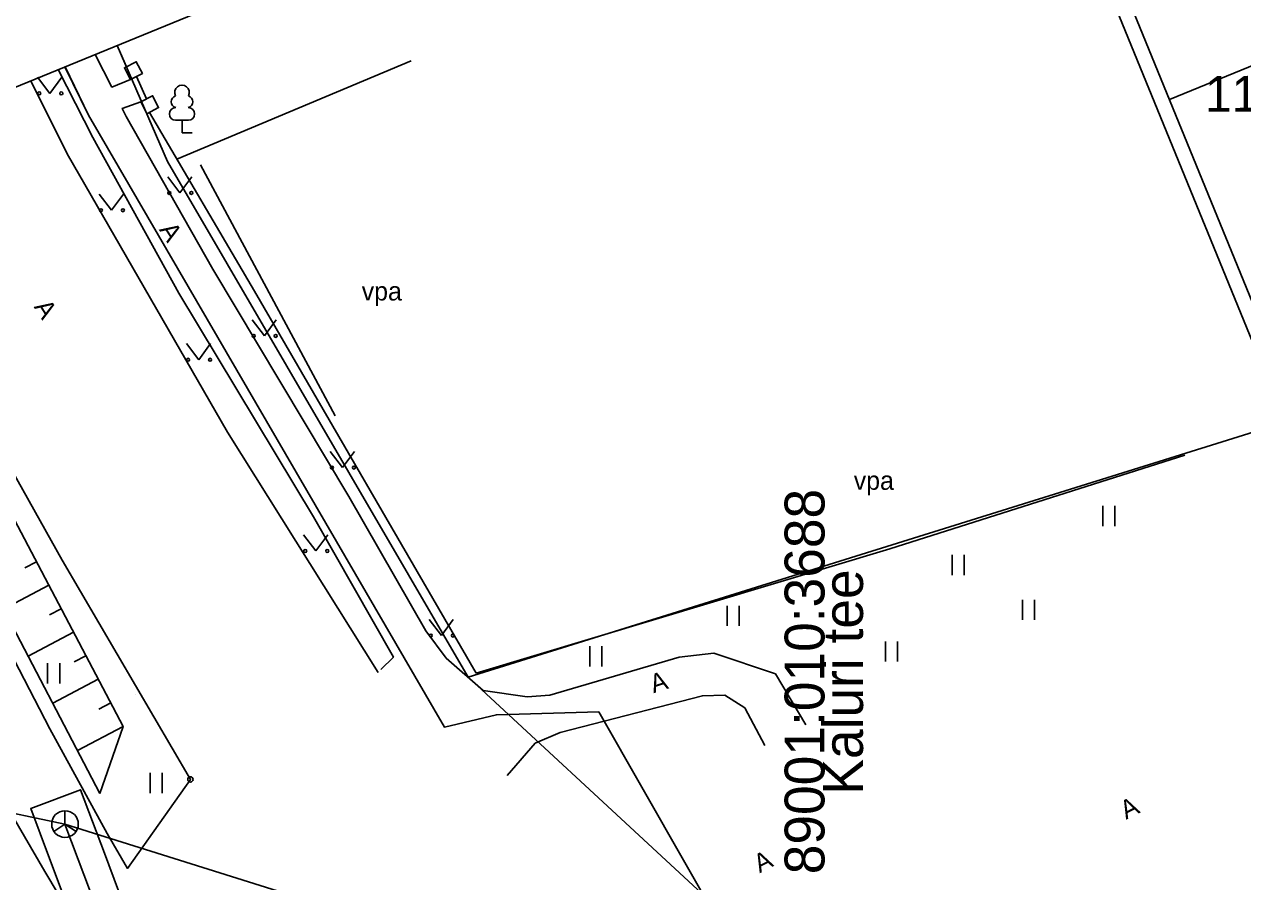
# Model space of a CAD drawing. Extents: x -52238384 to 549205, y 6582846 to 57187752.
# Drawn here: x 546520.53 to 546566.37, y 6597206.32 to 6597238.57 of the extents above; entities that cross this region are included whole.
import ezdxf

# ---------------------------------------------------------------- set-up
doc = ezdxf.new("R2010")
doc.units = 0
for name, color, linetype in [('_R-KATEND-TYYP 1 - ASFALT-SOIDUTEE (Kaluri-Kivila)', 7, 'Continuous'), ('kaluri tee mõõdistus$0$AED', 7, 'Continuous'), ('kaluri tee mõõdistus$0$HALJASTUS', 7, 'Continuous'), ('kaluri tee mõõdistus$0$KORGUS-EH2000', 7, 'Continuous'), ('kaluri tee mõõdistus$0$PUU', 7, 'Continuous'), ('kaluri tee mõõdistus$0$Reljeef', 7, 'Continuous'), ('kaluri tee mõõdistus$0$SIKAEV', 7, 'Continuous'), ('kaluri tee mõõdistus$0$SITRASS', 7, 'Continuous'), ('kaluri tee mõõdistus$0$TEE', 7, 'Continuous'), ('Kasutusala', 7, 'Continuous'), ('L_AADRESS', 7, 'Continuous'), ('Level 52', 7, 'Continuous'), ('Level 63', 7, 'Continuous'), ('PIIR', 7, 'Continuous'), ('TUNNUS', 7, 'Continuous'), ('VORMISTUS', 7, 'Continuous')]:
    doc.layers.add(name, color=color, linetype=linetype)

# ---------------------------------------------------------------- blocks, each defined once
blk = doc.blocks.new('kaluri tee mõõdistus$0$HEIN')
at = {"layer": 'kaluri tee mõõdistus$0$HALJASTUS'}
for p, q in [((-45.5, 76.1), (-45.5, -76.1)), ((45.5, 76.1), (45.5, -76.1))]:
    blk.add_line(p, q, dxfattribs=at)
blk = doc.blocks.new('kaluri tee mõõdistus$0$MURU')
at = {"layer": 'kaluri tee mõõdistus$0$HALJASTUS'}
for p, q in [((-92.7, 121.3), (0, 0)), ((0, 0), (89.1, 121.3))]:
    blk.add_line(p, q, dxfattribs=at)
for centre in [(-80.2, 0), (85.5, 0)]:
    blk.add_circle(centre, 11, dxfattribs=at)
blk = doc.blocks.new('kaluri tee mõõdistus$0$LEHTP1')
at = {"layer": 'kaluri tee mõõdistus$0$PUU'}
for p, q in [((48, 95), (-48, 95)), ((0, 0), (0, 95)), ((76, 0), (0, 0))]:
    blk.add_line(p, q, dxfattribs=at)
for centre, radius, start, end in [((-34, 234.5), 46.5, 109.02174, 253.14154), ((0, 304), 55.4, 332.5799, 207.4201), ((34, 234.5), 46.5, 286.85082, 70.98591), ((-47.5, 142.5), 47.5, 90.0016, 269.3953), ((47.5, 142.5), 47.5, 270.6047, 89.9984)]:
    blk.add_arc(centre, radius, start, end, dxfattribs=at)
blk = doc.blocks.new('kaluri tee mõõdistus$0$SIKAEV')
at = {"layer": 'kaluri tee mõõdistus$0$SIKAEV'}
for p, q in [((0, 100), (0, 0)), ((0, 0), (-83, -55)), ((0, 0), (83, -55))]:
    blk.add_line(p, q, dxfattribs=at)
blk.add_circle((0, 0), 100, dxfattribs=at)
blk = doc.blocks.new('kaluri tee mõõdistus$0$RING02_1')
at = {"layer": 'kaluri tee mõõdistus$0$KORGUS-EH2000'}
blk.add_circle((0, 0), 20, dxfattribs=at)

msp = doc.modelspace()

# ---------------------------------------------------------------- linework, layer by layer
at = {"layer": '_R-KATEND-TYYP 1 - ASFALT-SOIDUTEE (Kaluri-Kivila)'}
msp.add_arc((546525.884, 6597215.009), 2.036, 234.4708, 234.5095, dxfattribs=at)
at = {"layer": 'kaluri tee mõõdistus$0$AED'}
msp.add_line((546524.369, 6597236.977), (546524.018, 6597237.78), dxfattribs=at)
for points in [[(546524.526, 6597236.495), (546524.294, 6597236.938), (546524.737, 6597237.169), (546524.969, 6597236.726), (546524.526, 6597236.495)], [(546526.265, 6597233.503), (546535.081, 6597237.198)], [(546524.747, 6597236.611), (546525.127, 6597235.768)], [(546525.137, 6597235.209), (546524.906, 6597235.652), (546525.349, 6597235.884), (546525.58, 6597235.441), (546525.137, 6597235.209)], [(546537.529, 6597214.157), (546529.185, 6597228.529), (546525.234, 6597235.259)], [(546564.188, 6597222.369), (546553.096, 6597218.834), (546537.529, 6597214.157)]]:
    msp.add_lwpolyline(points, dxfattribs=at)
at = {"layer": 'kaluri tee mõõdistus$0$HALJASTUS'}
msp.add_lwpolyline([(546532.216, 6597223.842), (546527.155, 6597233.292)], dxfattribs=at)
at = {"layer": 'kaluri tee mõõdistus$0$Reljeef'}
for p, q in [((546523.368, 6597209.639), (546511.346, 6597232.595)), ((546520.539, 6597218.123), (546520.981, 6597218.355)), ((546519.738, 6597216.571), (546521.447, 6597217.47)), ((546521.47, 6597216.353), (546521.913, 6597216.585)), ((546520.665, 6597214.799), (546522.378, 6597215.7)), ((546522.401, 6597214.583), (546522.844, 6597214.815)), ((546521.593, 6597213.027), (546523.309, 6597213.93)), ((546523.332, 6597212.813), (546523.775, 6597213.045)), ((546522.521, 6597211.256), (546524.241, 6597212.16))]:
    msp.add_line(p, q, dxfattribs=at)
msp.add_lwpolyline([(546513.11, 6597233.316), (546524.241, 6597212.16), (546523.368, 6597209.639)], dxfattribs=at)
at = {"layer": 'kaluri tee mõõdistus$0$SITRASS'}
for points in [[(546542.14, 6597212.709), (546538.29, 6597212.6), (546536.33, 6597212.13), (546522.94, 6597235.16), (546522.056, 6597236.978)], [(546542.14, 6597212.709), (546538.29, 6597212.6), (546536.33, 6597212.13), (546522.94, 6597235.16), (546522.057, 6597236.978)], [(546566.11, 6597172.916), (546564.327, 6597177.131), (546559.046, 6597186.14), (546548.663, 6597201.281), (546542.14, 6597212.709)], [(546548.663, 6597201.281), (546548.11, 6597201.65), (546545.89, 6597202.29), (546531.554, 6597205.491), (546522.056, 6597208.484), (546511.376, 6597210.741)]]:
    msp.add_lwpolyline(points, dxfattribs=at)
at = {"layer": 'kaluri tee mõõdistus$0$TEE'}
for points in [[(546523.195, 6597237.444), (546523.822, 6597236.213), (546524.526, 6597236.495)], [(546533.945, 6597214.3), (546534.416, 6597214.76), (546531.408, 6597220.04), (546526.336, 6597228.454), (546523.1, 6597234.312), (546521.802, 6597236.873)], [(546520.772, 6597236.452), (546522.144, 6597233.703), (546528.17, 6597223.227), (546533.837, 6597214.187)], [(546549.937, 6597212.222), (546548.788, 6597214.136), (546546.47, 6597214.912), (546545.165, 6597214.758), (546540.303, 6597213.34), (546539.443, 6597213.273), (546537.795, 6597213.515), (546536.393, 6597214.729), (546535.637, 6597215.749), (546532.74, 6597220.807), (546527.624, 6597229.365), (546524.355, 6597235.107), (546524.209, 6597235.41), (546524.906, 6597235.652)], [(546510.834, 6597232.385), (546511.564, 6597230.966), (546516.471, 6597221.744), (546521.48, 6597212.062), (546523.639, 6597208.124), (546524.412, 6597206.815), (546526.775, 6597210.165), (546521.944, 6597218.407), (546515.01, 6597230.79), (546513.582, 6597233.51)], [(546473.034, 6597193.848), (546473.679, 6597191.418), (546474.667, 6597190.222), (546475.266, 6597189.855), (546482.67, 6597192.141), (546485.882, 6597193.259), (546486.464, 6597193.742), (546486.212, 6597195.569), (546485.561, 6597197.791), (546488.008, 6597198.596), (546488.751, 6597195.981), (546489.598, 6597194.886), (546490.075, 6597194.545), (546495.577, 6597196.146), (546509.496, 6597200.439), (546517.764, 6597203.312), (546522.268, 6597205.075), (546521.293, 6597206.702), (546518.984, 6597210.646), (546513.99, 6597220.048), (546509.053, 6597229.628), (546508.194, 6597231.305)], [(546548.39, 6597211.446), (546547.632, 6597212.856), (546546.884, 6597213.334), (546546.043, 6597213.309), (546540.693, 6597211.926), (546539.753, 6597211.531), (546538.697, 6597210.312)]]:
    msp.add_lwpolyline(points, dxfattribs=at)
at = {"layer": 'Kasutusala'}
msp.add_lwpolyline([(546524.436, 6597204.996), (546523.538, 6597207.384), (546522.64, 6597209.772), (546520.768, 6597209.068), (546521.436, 6597207.292), (546522.103, 6597205.516), (546521.227, 6597204.663), (546519.52, 6597203.964), (546517.813, 6597203.264), (546514.825, 6597202.225), (546511.837, 6597201.185), (546512.915, 6597198.64), (546515.76, 6597191.92), (546517.23, 6597192.37), (546515.859, 6597196.18), (546514.488, 6597199.99), (546516.505, 6597200.691), (546518.522, 6597201.393), (546520.433, 6597202.176), (546522.345, 6597202.96), (546523.39, 6597203.978)], close=True, dxfattribs=at)
at = {"layer": 'Level 52'}
msp.add_lwpolyline([(546556.701, 6597251.154), (546585.474, 6597180.84), (546491.483, 6597142.378), (546462.71, 6597212.692)], close=True, dxfattribs=at)
at = {"layer": 'Level 63'}
msp.add_lwpolyline([(546512.228, 6597200.262), (546518.168, 6597202.329), (546521.786, 6597203.811), (546523.27, 6597205.256), (546522.056, 6597208.484)], dxfattribs=at)
at = {"layer": 'PIIR'}
for points in [[(546524.023, 6597237.782), (546525.91, 6597233.41), (546537.23, 6597214.01), (546552.45, 6597199.91), (546566.856, 6597173.221)], [(546567.974, 6597223.606), (546537.23, 6597214.01), (546525.91, 6597233.41), (546524.023, 6597237.782)], [(546574.352, 6597208.02), (546552.45, 6597199.91), (546537.23, 6597214.01), (546567.974, 6597223.606)]]:
    msp.add_lwpolyline(points, dxfattribs=at)
at = {"layer": 'VORMISTUS'}
msp.add_line((546575.365, 6597240.561), (546563.612, 6597235.752), dxfattribs=at)
msp.add_lwpolyline([(546565.697, 6597264.186), (546600.955, 6597178.026), (546589.203, 6597173.216), (546553.945, 6597259.377)], close=True, dxfattribs=at)

# ---------------------------------------------------------------- block references
at = {"layer": 'kaluri tee mõõdistus$0$HALJASTUS', "xscale": 0.005000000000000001, "yscale": 0.005000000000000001, "rotation": -4.073594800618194e-10}
for name, p in [('kaluri tee mõõdistus$0$MURU', (546521.49, 6597235.977)), ('kaluri tee mõõdistus$0$MURU', (546526.383, 6597232.23)), ('kaluri tee mõõdistus$0$MURU', (546523.809, 6597231.578)), ('kaluri tee mõõdistus$0$MURU', (546529.557, 6597226.852)), ('kaluri tee mõõdistus$0$MURU', (546527.088, 6597225.953)), ('kaluri tee mõõdistus$0$MURU', (546532.501, 6597221.898)), ('kaluri tee mõõdistus$0$HEIN', (546561.33, 6597220.073)), ('kaluri tee mõõdistus$0$MURU', (546531.496, 6597218.759)), ('kaluri tee mõõdistus$0$HEIN', (546555.661, 6597218.23)), ('kaluri tee mõõdistus$0$HEIN', (546558.315, 6597216.546)), ('kaluri tee mõõdistus$0$HEIN', (546547.198, 6597216.317)), ('kaluri tee mõõdistus$0$MURU', (546536.222, 6597215.577)), ('kaluri tee mõõdistus$0$HEIN', (546542.031, 6597214.792)), ('kaluri tee mõõdistus$0$HEIN', (546553.157, 6597214.977)), ('kaluri tee mõõdistus$0$HEIN', (546521.629, 6597214.151)), ('kaluri tee mõõdistus$0$HEIN', (546525.49, 6597210.025))]:
    msp.add_blockref(name, p, dxfattribs=at)
at = {"layer": 'kaluri tee mõõdistus$0$KORGUS-EH2000', "xscale": 0.005000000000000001, "yscale": 0.005000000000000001, "rotation": -4.073594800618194e-10}
msp.add_blockref('kaluri tee mõõdistus$0$RING02_1', (546526.775, 6597210.165), dxfattribs=at)
at = {"layer": 'kaluri tee mõõdistus$0$PUU', "xscale": 0.005000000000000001, "yscale": 0.005000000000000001, "rotation": -4.073594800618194e-10}
msp.add_blockref('kaluri tee mõõdistus$0$LEHTP1', (546526.459, 6597234.491), dxfattribs=at)
at = {"layer": 'kaluri tee mõõdistus$0$SIKAEV', "xscale": 0.005000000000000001, "yscale": 0.005000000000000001, "rotation": -4.073594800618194e-10}
msp.add_blockref('kaluri tee mõõdistus$0$SIKAEV', (546522.056, 6597208.484), dxfattribs=at)

# ---------------------------------------------------------------- texts
at = {"layer": 'kaluri tee mõõdistus$0$HALJASTUS'}
for p in [(546533.222, 6597228.184), (546551.736, 6597221.06)]:
    msp.add_text('vpa', height=0.7, rotation=360, dxfattribs=at).set_placement(p)
at = {"layer": 'kaluri tee mõõdistus$0$TEE'}
for rotation, p in [(302.6003, (546525.582, 6597230.848)), (302.6003, (546520.87, 6597227.943)), (17.7069, (546544.201, 6597213.404)), (26.8592, (546561.983, 6597208.642)), (26.8592, (546548.195, 6597206.632))]:
    msp.add_text('A', height=0.7, rotation=rotation, dxfattribs=at).set_placement(p)
at = {"layer": 'L_AADRESS'}
msp.add_text('11251 Viimsi-Rohuneeme tee', height=1.35, rotation=0.1241, dxfattribs=at).set_placement((546564.955, 6597235.283))
at = {"layer": 'TUNNUS'}
for s, p in [('89001:010:3688', (546550.634, 6597206.595)), ('Kaluri tee', (546552.083, 6597209.592))]:
    msp.add_text(s, height=1.5, rotation=90, dxfattribs=at).set_placement(p)

doc.saveas('drawing.dxf')
